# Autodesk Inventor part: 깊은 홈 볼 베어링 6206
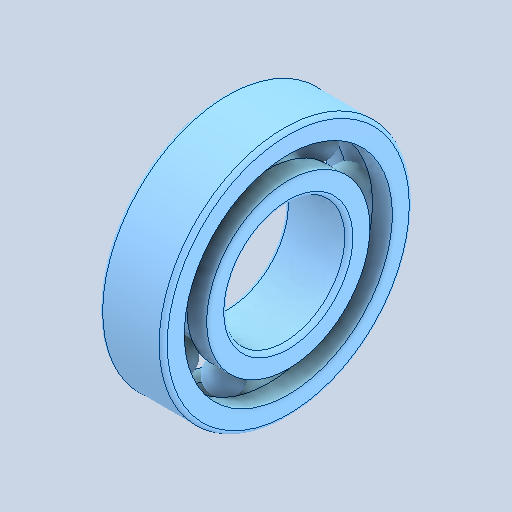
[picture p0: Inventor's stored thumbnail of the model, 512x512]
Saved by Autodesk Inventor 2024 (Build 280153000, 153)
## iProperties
Created: 2025-05
Part Number: 깊은 홈 볼 베어링 6206
Material: 강철, 연강
Description: 깊은 그루부 볼 베어링
Document SubType Name: Modeling
Designer: 11
Density: 7.85 g/cm^3
Appearance: 기본값
Author: jhkim
Sending System: Autodesk Inventor 2026
Preprocessor: ST-DEVELOPER v20.1
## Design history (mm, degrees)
node "깊은 홈 볼 베어링 62061"
node "솔리드1"
node "솔리드2"
node "솔리드3"
node "솔리드4"
node "솔리드5"
node "솔리드6"
node "솔리드7"
node "솔리드8"
node "솔리드9"
node "솔리드10"
node "솔리드11"
body "Solid1"
node "Solid1:1"
node "Solid1:2"
node "Solid1:3"
node "Solid1:4"
node "Solid1:5"
node "Solid1:6"
node "Solid1:7"
node "Solid1:8"
node "Solid1:9"
node "Solid1:10"
